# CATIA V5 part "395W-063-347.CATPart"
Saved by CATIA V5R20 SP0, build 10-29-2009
Part number: 395W-063-347
Bounding box of the stored display mesh (mm): x -14 to 333, y -39.01 to 37.5, z -37.5 to 37.5
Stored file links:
  C:\Users\Raffaele\Desktop\3D X SITO CF\PERNI -STAFFE SOLLEVAMENTO\395W\395W-063-347.CATPart
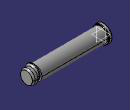
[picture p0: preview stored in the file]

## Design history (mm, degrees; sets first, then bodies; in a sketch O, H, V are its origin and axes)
Body1 (main body)
  Solid1 "ImportedBody": solid without history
